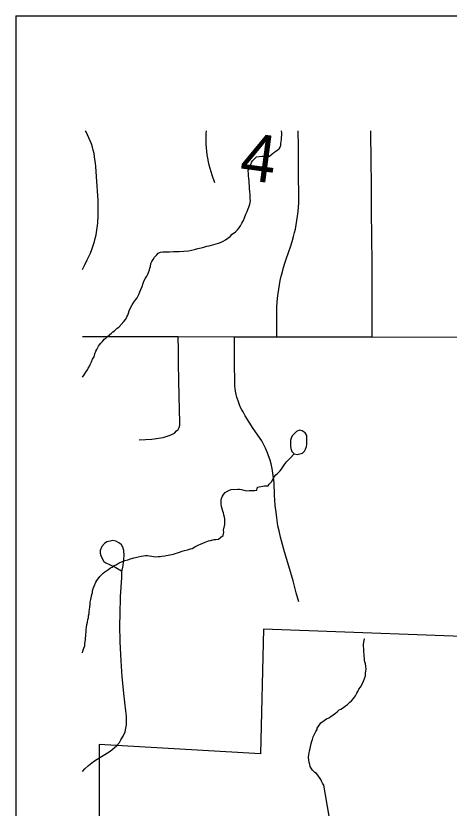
# Model space of a CAD drawing. Extents: x -11.4 to 84.1, y 11.1 to 59.
# Drawn here: x 26.165 to 26.686, y 46.596 to 47.548 of the extents above; entities that cross this region are included whole.
import ezdxf

# ---------------------------------------------------------------- set-up
doc = ezdxf.new("R2010")
doc.units = 0
for name, color, linetype in [('GM_X_Corporation', 7, 'Continuous'), ('GM_X_Minor_Lake', 7, 'Continuous'), ('GM_X_Minor_River', 7, 'Continuous'), ('GM_X_Township_Road', 7, 'Continuous'), ('GM_X_Township_Road_Text', 7, 'Continuous'), ('SH_Data', 7, 'Continuous')]:
    doc.layers.add(name, color=color, linetype=linetype)

msp = doc.modelspace()

# ---------------------------------------------------------------- linework, layer by layer
at = {"layer": 'GM_X_Corporation'}
msp.add_line((26.26551, 46.67282), (26.26551, 44.98318), dxfattribs=at)
msp.add_lwpolyline([(26.76735, 46.80026), (26.46289, 46.81152), (26.45958, 46.66172), (26.26551, 46.67282)], dxfattribs=at)
at = {"layer": 'GM_X_Minor_Lake'}
for points in [[(26.51515, 47.04272), (26.51499, 47.04414), (26.51307, 47.04753), (26.50965, 47.04978), (26.50624, 47.05051), (26.50285, 47.04896), (26.49985, 47.04628), (26.4976, 47.04361), (26.49648, 47.04095), (26.49575, 47.03829), (26.4954, 47.03487), (26.49543, 47.03146), (26.49583, 47.02843), (26.49699, 47.02503), (26.50004, 47.02202), (26.50344, 47.0213)], [(26.51506, 47.03342), (26.51515, 47.04272)], [(26.50344, 47.0213), (26.50684, 47.02208), (26.50986, 47.02287), (26.51249, 47.02517), (26.5136, 47.02783), (26.51471, 47.03087), (26.51506, 47.03342)]]:
    msp.add_lwpolyline(points, dxfattribs=at)
at = {"layer": 'GM_X_Minor_River'}
for points in [[(26.38029, 47.2675), (26.38407, 47.2687), (26.38823, 47.26953), (26.39126, 47.27034), (26.39504, 47.27154), (26.39769, 47.27196), (26.40071, 47.27277), (26.40336, 47.27358), (26.406, 47.27438), (26.40903, 47.27519), (26.41205, 47.27638), (26.41469, 47.27756), (26.41732, 47.27912), (26.42033, 47.28107), (26.42295, 47.28301), (26.42556, 47.28609), (26.42931, 47.28881), (26.43193, 47.29113), (26.43379, 47.29345), (26.43527, 47.29613), (26.43711, 47.2992), (26.43896, 47.30227), (26.44042, 47.30571), (26.44187, 47.30991), (26.44333, 47.31336), (26.44444, 47.31566), (26.44553, 47.31833), (26.44661, 47.32215), (26.4473, 47.32596), (26.44725, 47.329), (26.44721, 47.33128), (26.44717, 47.33394), (26.44673, 47.33735), (26.44629, 47.34077), (26.44624, 47.34418), (26.44581, 47.34684), (26.44575, 47.35025), (26.44533, 47.35291), (26.4449, 47.35594), (26.44486, 47.3586), (26.44479, 47.3624), (26.44587, 47.36622), (26.44735, 47.36852), (26.44881, 47.37196), (26.44991, 47.37426), (26.45253, 47.37696), (26.45477, 47.3789), (26.4616, 47.37977), (26.46729, 47.37986), (26.47033, 47.37991), (26.4737, 47.38263), (26.47558, 47.38417), (26.47783, 47.38573), (26.47971, 47.3869), (26.48196, 47.38846), (26.48307, 47.39037), (26.48378, 47.39305), (26.48375, 47.39495), (26.48481, 47.3999), (26.48477, 47.40218), (26.4851, 47.40485), (26.48505, 47.40789), (26.48464, 47.40978), (26.48454, 47.41026)], [(26.2454, 47.11425), (26.24759, 47.11717), (26.24943, 47.12024), (26.25129, 47.12293), (26.2524, 47.12485), (26.2535, 47.12677), (26.2546, 47.12944), (26.25607, 47.13251), (26.25753, 47.13595), (26.25938, 47.13864), (26.26047, 47.14208), (26.26155, 47.14551), (26.26265, 47.14743), (26.26487, 47.15127), (26.26598, 47.15319), (26.26746, 47.15511), (26.26933, 47.15704), (26.27157, 47.15974), (26.27382, 47.16129), (26.27568, 47.16322), (26.2783, 47.16554), (26.28018, 47.16709), (26.28205, 47.16864), (26.28393, 47.16981), (26.2873, 47.17291), (26.28917, 47.17446), (26.29514, 47.18102), (26.29737, 47.18371), (26.29884, 47.18677), (26.29995, 47.18869), (26.30067, 47.19098), (26.30176, 47.19404), (26.30322, 47.19749), (26.30506, 47.20093), (26.30728, 47.20439), (26.30951, 47.20747), (26.311, 47.20939), (26.3121, 47.21131), (26.3132, 47.2136), (26.31429, 47.21666), (26.31576, 47.21973), (26.31722, 47.22317), (26.3183, 47.22699), (26.31976, 47.23043), (26.32123, 47.23311), (26.32272, 47.23542), (26.32381, 47.23809), (26.32492, 47.24001), (26.32601, 47.24307), (26.32635, 47.24497), (26.32708, 47.24727), (26.32778, 47.2507), (26.32888, 47.253), (26.33035, 47.25568), (26.33221, 47.25837), (26.33482, 47.26107), (26.3363, 47.26337), (26.33932, 47.26456), (26.34198, 47.26461), (26.34464, 47.26465), (26.34729, 47.26469), (26.34995, 47.26474), (26.35488, 47.26519), (26.3583, 47.26525), (26.36172, 47.2653), (26.37272, 47.26586), (26.37651, 47.26668), (26.38029, 47.2675)], [(26.4322, 46.97955), (26.4341, 46.97958), (26.43676, 46.97924), (26.43943, 46.97853), (26.44134, 46.97818), (26.44324, 46.97783), (26.4459, 46.97787), (26.4478, 46.9779), (26.4497, 46.97793), (26.45236, 46.97798), (26.45501, 46.9784), (26.4557, 46.98221), (26.46442, 46.98349), (26.4686, 46.98356), (26.47008, 46.98548), (26.47269, 46.98856), (26.47528, 46.99278), (26.47638, 46.9947), (26.47786, 46.997), (26.47974, 46.99856), (26.48273, 47.00126), (26.48459, 47.00357), (26.48607, 47.00588), (26.48829, 47.00933), (26.4909, 47.01242), (26.49314, 47.01473), (26.495, 47.01704), (26.50004, 47.02202)], [(26.25004, 46.81094), (26.25038, 46.81361), (26.2507, 46.81703), (26.25141, 46.82008), (26.25174, 46.82313), (26.25247, 46.82504), (26.25281, 46.82733), (26.25352, 46.83038), (26.25349, 46.83228), (26.25381, 46.8357), (26.25415, 46.83799), (26.25447, 46.84141), (26.25481, 46.84408), (26.25552, 46.84713), (26.25621, 46.85094), (26.25656, 46.85323), (26.25728, 46.85514), (26.25762, 46.85742), (26.25833, 46.86047), (26.25943, 46.86315), (26.26163, 46.86775), (26.26273, 46.87004), (26.26422, 46.87197), (26.26645, 46.87466), (26.26869, 46.87698), (26.27018, 46.8789), (26.27243, 46.88046), (26.27468, 46.88202), (26.27694, 46.88357), (26.27919, 46.88513), (26.28108, 46.88592), (26.2837, 46.88786), (26.28597, 46.88866), (26.28935, 46.89099), (26.29237, 46.89218), (26.29463, 46.89298), (26.29651, 46.89415), (26.29992, 46.89496), (26.30332, 46.89616), (26.3071, 46.89698), (26.30899, 46.89739), (26.3124, 46.8982), (26.31618, 46.89902), (26.31883, 46.89945), (26.3211, 46.89986), (26.32376, 46.89991), (26.32605, 46.89956), (26.32871, 46.89923), (26.331, 46.89888), (26.33328, 46.89854), (26.33632, 46.89859), (26.33898, 46.89863), (26.34087, 46.89904), (26.34428, 46.89948), (26.34617, 46.89989), (26.35299, 46.90114), (26.35488, 46.90155), (26.35677, 46.90234), (26.35979, 46.90315), (26.36206, 46.90394), (26.36546, 46.90514), (26.3681, 46.90594), (26.37188, 46.90676), (26.37528, 46.90795), (26.37718, 46.90837), (26.38056, 46.91032), (26.38282, 46.9115), (26.38546, 46.91268), (26.38734, 46.91347), (26.38998, 46.91465), (26.393, 46.91584), (26.39489, 46.91663), (26.39715, 46.91743), (26.39943, 46.91784), (26.40358, 46.91905), (26.40586, 46.91909), (26.40889, 46.91952), (26.41189, 46.92184), (26.41451, 46.92417), (26.41521, 46.92798), (26.41517, 46.93026), (26.41658, 46.93712), (26.41654, 46.9394), (26.41649, 46.94206), (26.41646, 46.94396), (26.41605, 46.94585), (26.41524, 46.94888), (26.41482, 46.95115), (26.41403, 46.95304), (26.41322, 46.95606), (26.41242, 46.95871), (26.41237, 46.96137), (26.41229, 46.96631), (26.41263, 46.9686), (26.41373, 46.97127), (26.41483, 46.97319), (26.41708, 46.97551), (26.4197, 46.97745), (26.42234, 46.97863), (26.42422, 46.97942), (26.4322, 46.97955)], [(26.2454, 46.78318), (26.24592, 46.78504), (26.247, 46.78847), (26.24809, 46.79153), (26.24843, 46.7942), (26.24877, 46.7961), (26.2491, 46.79915), (26.24907, 46.80105), (26.24942, 46.80295), (26.24938, 46.80523), (26.24971, 46.80828), (26.25004, 46.81094)], [(26.54217, 46.58675), (26.53575, 46.62403), (26.53419, 46.62667), (26.53301, 46.62893), (26.53222, 46.63081), (26.52833, 46.63607), (26.52678, 46.63795), (26.52486, 46.63943), (26.52216, 46.64205), (26.5206, 46.64431), (26.51904, 46.64656), (26.51863, 46.64883), (26.51781, 46.65186), (26.5174, 46.65413), (26.51734, 46.65755), (26.51767, 46.6606), (26.51801, 46.66288), (26.51835, 46.66517), (26.51906, 46.66822), (26.51941, 46.67013), (26.52014, 46.67204), (26.52048, 46.67394), (26.52119, 46.67699), (26.52192, 46.67891), (26.523, 46.68234), (26.5241, 46.68464), (26.52594, 46.68847), (26.5278, 46.69078), (26.52777, 46.69268), (26.52962, 46.69537), (26.53184, 46.69882), (26.53597, 46.70193), (26.53897, 46.70388), (26.54161, 46.70506), (26.54387, 46.70662), (26.54687, 46.70857), (26.5495, 46.71051), (26.55175, 46.71206), (26.55399, 46.71438), (26.55626, 46.71518), (26.55926, 46.71751), (26.5615, 46.71944), (26.56414, 46.721), (26.56675, 46.72371), (26.569, 46.72526), (26.57123, 46.72834), (26.57384, 46.73142), (26.57531, 46.73448), (26.57641, 46.73678), (26.57788, 46.73946), (26.57974, 46.74177), (26.58194, 46.74637), (26.58342, 46.74905), (26.58559, 46.75555), (26.58592, 46.75859), (26.58625, 46.76126), (26.5866, 46.76317), (26.58616, 46.76696), (26.58573, 46.76999), (26.58493, 46.77226), (26.58452, 46.77415), (26.58449, 46.77605), (26.58405, 46.77946), (26.58356, 46.78592), (26.58344, 46.79313), (26.58412, 46.79808), (26.58447, 46.79999), (26.58485, 46.8)]]:
    msp.add_lwpolyline(points, dxfattribs=at)
at = {"layer": 'GM_X_Township_Road'}
for points in [[(26.2454, 47.24355), (26.2455, 47.24374), (26.24797, 47.24842), (26.25124, 47.25524), (26.25505, 47.26325), (26.25672, 47.26753), (26.25832, 47.27247), (26.25973, 47.27735), (26.26073, 47.28082), (26.26173, 47.2853), (26.26267, 47.29071), (26.26373, 47.29933), (26.26441, 47.30835), (26.26427, 47.32646), (26.26244, 47.35525), (26.2614, 47.36728), (26.26099, 47.37129), (26.26046, 47.37563), (26.25993, 47.37931), (26.25936, 47.38296), (26.25842, 47.38682), (26.25733, 47.39064), (26.2561, 47.39442), (26.25477, 47.39815), (26.25326, 47.40182), (26.25165, 47.40545), (26.24985, 47.409), (26.24916, 47.41026)], [(26.4047, 47.34749), (26.40144, 47.35677), (26.40007, 47.3608), (26.39888, 47.36486), (26.39779, 47.36897), (26.39685, 47.3731), (26.396, 47.37726), (26.39534, 47.38146), (26.39482, 47.38567), (26.3944, 47.38989), (26.39416, 47.39413), (26.39402, 47.39837), (26.39421, 47.40685), (26.39444, 47.41026)], [(26.47929, 47.16281), (26.47907, 47.18792), (26.47926, 47.19862), (26.4796, 47.20396), (26.48003, 47.20929), (26.48064, 47.21461), (26.48136, 47.2199), (26.48226, 47.22518), (26.4833, 47.23043), (26.48444, 47.23565), (26.48577, 47.24084), (26.4872, 47.24599), (26.48876, 47.25111), (26.49052, 47.25617), (26.49579, 47.2719), (26.49739, 47.27709), (26.49923, 47.28328), (26.50038, 47.28787), (26.50143, 47.29195), (26.50248, 47.2972), (26.50333, 47.30247), (26.50409, 47.30778), (26.50466, 47.3131), (26.50514, 47.31843), (26.50542, 47.32377), (26.50561, 47.32911), (26.50534, 47.36018), (26.50506, 47.39125), (26.50489, 47.40991), (26.50489, 47.41026)], [(26.59374, 47.16259), (26.59364, 47.17398), (26.59391, 47.19798), (26.59375, 47.22465), (26.59359, 47.25133), (26.59331, 47.2824), (26.59303, 47.31347), (26.59275, 47.34453), (26.59247, 47.3756), (26.5922, 47.40667), (26.59216, 47.41026)], [(26.2454, 47.1632), (26.33645, 47.16302), (26.36057, 47.16294), (26.42807, 47.16287), (26.47929, 47.16281), (26.59374, 47.16259), (26.71623, 47.16224)], [(26.31361, 47.03908), (26.32872, 47.03978), (26.34254, 47.04187), (26.35079, 47.04454), (26.3559, 47.0471), (26.35846, 47.04966), (26.36044, 47.0514), (26.36151, 47.05357), (26.36231, 47.05667), (26.36255, 47.05986), (26.36177, 47.09092), (26.36128, 47.11078), (26.36079, 47.13065), (26.36068, 47.1468), (26.36057, 47.16294)], [(26.50545, 46.84437), (26.50232, 46.85509), (26.49872, 46.86965), (26.49359, 46.88704), (26.48846, 46.90444), (26.48343, 46.92201), (26.48179, 46.9296), (26.48029, 46.93555), (26.47918, 46.94522), (26.4782, 46.95221), (26.47709, 46.96012), (26.47676, 46.96653), (26.47637, 46.97208), (26.47578, 46.98771), (26.47447, 46.99882), (26.47356, 47.00457), (26.47212, 47.01026), (26.47114, 47.0147), (26.46912, 47.01986), (26.46794, 47.02326), (26.46545, 47.02875), (26.46303, 47.03379), (26.46104, 47.03757), (26.45055, 47.05254), (26.441, 47.06758), (26.43846, 47.07254), (26.43708, 47.07509), (26.43558, 47.0779), (26.43421, 47.08117), (26.43316, 47.08463), (26.43094, 47.09006), (26.43009, 47.09339), (26.42931, 47.09732), (26.42872, 47.10378), (26.42846, 47.11058), (26.4284, 47.12817), (26.42833, 47.14575), (26.42807, 47.16287)], [(26.2454, 46.64039), (26.24807, 46.64354), (26.25272, 46.6477), (26.25876, 46.65253), (26.26297, 46.65512), (26.27244, 46.66083), (26.27875, 46.66508), (26.2835, 46.66897), (26.28674, 46.6718), (26.2898, 46.67529), (26.29164, 46.67866), (26.29438, 46.68314), (26.29657, 46.68831), (26.29753, 46.69251), (26.29817, 46.69653), (26.29854, 46.70116), (26.29826, 46.70695), (26.29753, 46.71345), (26.29534, 46.7342), (26.29438, 46.74279), (26.29328, 46.75422), (26.292, 46.77337), (26.29091, 46.79632), (26.29031, 46.81611), (26.29063, 46.82955), (26.29118, 46.85039), (26.29264, 46.87352), (26.2928, 46.88051), (26.29426, 46.88813), (26.2955, 46.89986), (26.29495, 46.90582), (26.29411, 46.90998), (26.29223, 46.91274), (26.29009, 46.91491), (26.28544, 46.91706), (26.28198, 46.91781), (26.27858, 46.91733), (26.27483, 46.91643), (26.27171, 46.91442), (26.26852, 46.91081), (26.26686, 46.90616), (26.26658, 46.90276), (26.26734, 46.89993), (26.26894, 46.89653), (26.27123, 46.89278), (26.27359, 46.89098), (26.27879, 46.88869), (26.28538, 46.88557), (26.29245, 46.88154)]]:
    msp.add_lwpolyline(points, dxfattribs=at)
at = {"layer": 'SH_Data'}
for q in [(33.16529, 47.54828), (26.16529, 40.54828)]:
    msp.add_line((26.16529, 47.54828), q, dxfattribs=at)

# ---------------------------------------------------------------- texts
at = {"layer": 'GM_X_Township_Road_Text'}
msp.add_text('4', height=0.05682, rotation=352.42552, dxfattribs=at).set_placement((26.43279, 47.35238))

doc.saveas('drawing.dxf')
